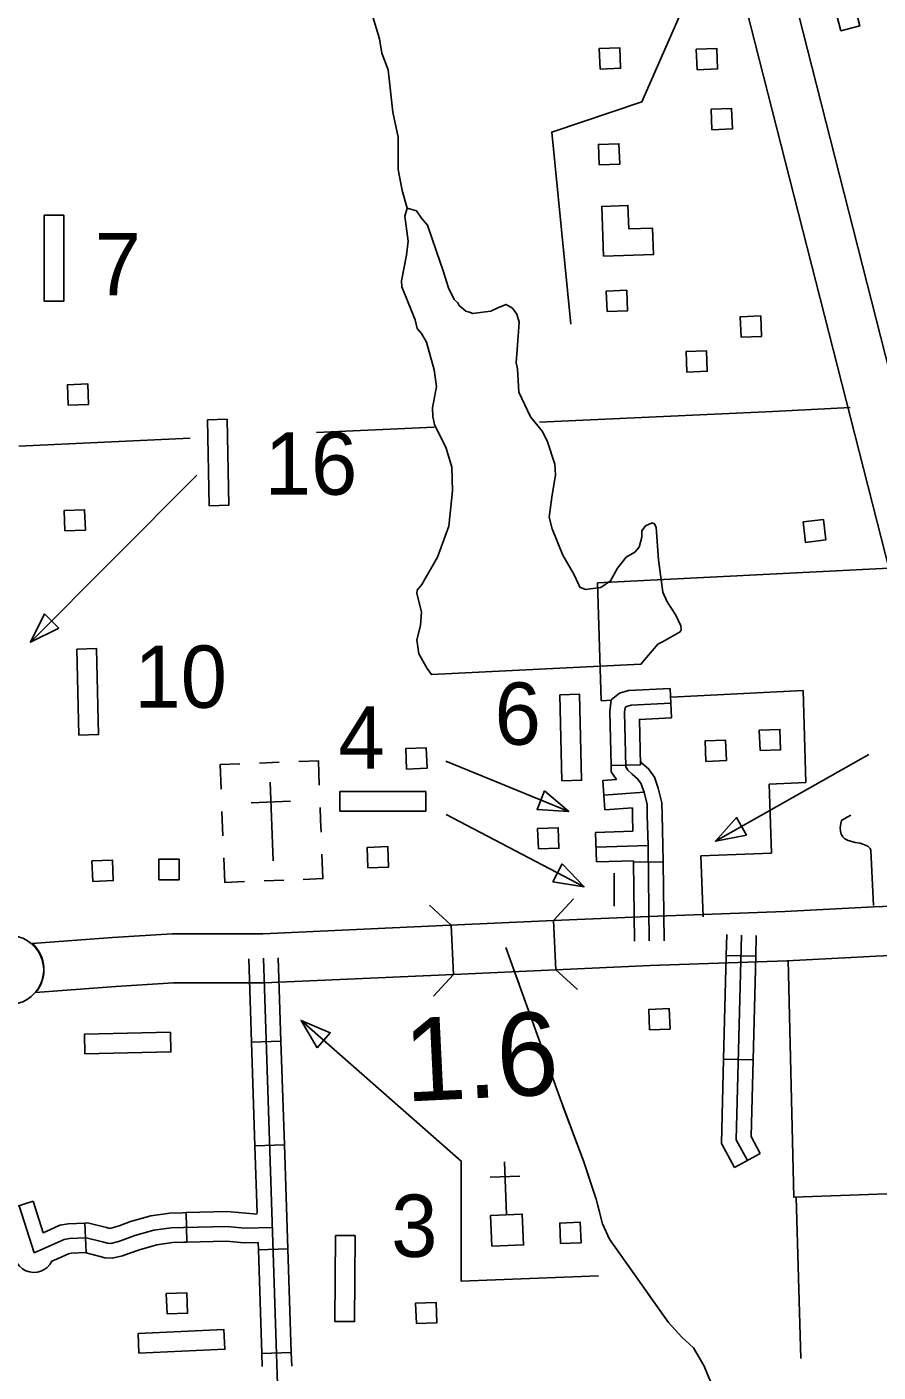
# Model space of a CAD drawing. Extents: x 1671357 to 13005564, y 567358 to 14261451.
# Drawn here: x 12758299.072 to 12758300.518, y 14259939.757 to 14259942.041 of the extents above; entities that cross this region are included whole.
import ezdxf

# ---------------------------------------------------------------- set-up
doc = ezdxf.new("R2010")
doc.units = 0
for name, color, linetype in [('10', 7, 'Continuous'), ('15', 7, 'Continuous'), ('24', 7, 'Continuous'), ('32', 7, 'Continuous'), ('34', 7, 'Continuous'), ('35', 7, 'Continuous'), ('37', 7, 'Continuous'), ('48', 7, 'Continuous'), ('5', 7, 'Continuous'), ('56', 7, 'Continuous'), ('58', 7, 'Continuous'), ('6', 7, 'Continuous')]:
    doc.layers.add(name, color=color, linetype=linetype)

msp = doc.modelspace()

# ---------------------------------------------------------------- linework, layer by layer
at = {"layer": '10'}
for p, q in [((12758299.7965, 14259940.4326), (12758299.7927, 14259940.516)), ((12758299.9707, 14259940.4405), (12758299.9664, 14259940.5238)), ((12758299.9704, 14259940.4404), (12758299.9667, 14259940.5238))]:
    msp.add_line(p, q, dxfattribs=at)
for points in [[(12758300.4677, 14259940.5447), (12758300.5105, 14259940.547), (12758300.6164, 14259940.5512), (12758300.6309, 14259940.5516), (12758300.6426, 14259940.5516), (12758300.6492, 14259940.5516), (12758300.6554, 14259940.5514), (12758300.6635, 14259940.551), (12758300.6733, 14259940.5502), (12758300.7026, 14259940.5476), (12758300.7417, 14259940.5439), (12758300.7807, 14259940.54), (12758300.7871, 14259940.5394), (12758300.7976, 14259940.5383), (12758300.8123, 14259940.537), (12758300.8849, 14259940.4463)], [(12758299.9664, 14259940.5238), (12758300.1277, 14259940.5311), (12758300.3593, 14259940.5391), (12758300.4677, 14259940.5447)], [(12758299.7908, 14259940.5159), (12758299.4729, 14259940.5016), (12758299.3186, 14259940.5016), (12758299.2174, 14259940.4953), (12758299.081, 14259940.485)], [(12758299.9664, 14259940.5238), (12758299.7908, 14259940.5159)], [(12758300.472, 14259940.4614), (12758300.3629, 14259940.4557), (12758300.131, 14259940.4477), (12758299.9707, 14259940.4405)], [(12758300.8849, 14259940.4463), (12758300.8734, 14259940.4474), (12758300.8502, 14259940.4496), (12758300.7895, 14259940.4553), (12758300.7788, 14259940.4563), (12758300.7726, 14259940.457), (12758300.7337, 14259940.4608), (12758300.6949, 14259940.4645), (12758300.666, 14259940.467), (12758300.658, 14259940.4677), (12758300.6523, 14259940.468), (12758300.648, 14259940.4681), (12758300.6426, 14259940.4681), (12758300.632, 14259940.4681), (12758300.6191, 14259940.4678), (12758300.5144, 14259940.4636), (12758300.472, 14259940.4614)], [(12758299.9707, 14259940.4405), (12758299.7969, 14259940.4326)], [(12758299.0868, 14259940.4018), (12758299.2231, 14259940.412), (12758299.3212, 14259940.4182), (12758299.4748, 14259940.4181), (12758299.7969, 14259940.4326)]]:
    msp.add_lwpolyline(points, dxfattribs=at)
msp.add_arc((12758299.0415, 14259940.4404), 0.0595, 319.4609, 48.4838, dxfattribs=at)
at = {"layer": '15'}
msp.add_lwpolyline([(12758300.2887, 14259942.4326), (12758300.6474, 14259941.0247), (12758300.6563, 14259940.9997), (12758300.6752, 14259940.9578), (12758300.5858, 14259940.9531), (12758300.5788, 14259940.9686), (12758300.5675, 14259941.0004), (12758300.2052, 14259942.4222)], dxfattribs=at)
at = {"layer": '24'}
msp.add_circle((12758299.0421, 14259940.44), 0.0584, dxfattribs=at)
at = {"layer": '32'}
for p, q in [((12758300.1645, 14259940.9182), (12758300.167, 14259940.8682)), ((12758300.0643, 14259940.7874), (12758300.1143, 14259940.7886)), ((12758300.0535, 14259940.712), (12758300.0501, 14259940.762)), ((12758300.0396, 14259940.6237), (12758300.038, 14259940.6737)), ((12758300.1025, 14259940.6233), (12758300.1526, 14259940.6239)), ((12758300.3101, 14259940.4635), (12758300.2601, 14259940.4648)), ((12758299.5036, 14259940.3191), (12758299.4535, 14259940.3174)), ((12758300.3055, 14259940.2873), (12758300.2555, 14259940.2886)), ((12758299.5094, 14259940.1429), (12758299.4594, 14259940.1412)), ((12758300.3179, 14259940.1286), (12758300.274, 14259940.1046)), ((12758299.0351, 14259940.0323), (12758299.0829, 14259940.0473)), ((12758299.3436, 14259939.9779), (12758299.3424, 14259940.028)), ((12758299.1729, 14259939.9603), (12758299.1702, 14259940.0103)), ((12758299.5153, 14259939.9667), (12758299.4653, 14259939.9651)), ((12758299.5212, 14259939.7905), (12758299.4711, 14259939.7889))]:
    msp.add_line(p, q, dxfattribs=at)
for points in [[(12758300.1645, 14259940.9182), (12758300.0941, 14259940.9148), (12758300.0788, 14259940.9101), (12758300.0647, 14259940.8986), (12758300.0621, 14259940.8791), (12758300.0643, 14259940.7874)], [(12758300.1658, 14259940.8932), (12758300.0984, 14259940.8899), (12758300.0908, 14259940.8876), (12758300.0882, 14259940.8855), (12758300.0872, 14259940.8777), (12758300.0894, 14259940.7847), (12758300.0929, 14259940.7795), (12758300.1002, 14259940.7727), (12758300.1095, 14259940.7647), (12758300.1155, 14259940.7562), (12758300.1178, 14259940.7493), (12758300.1204, 14259940.7417), (12758300.1256, 14259940.7208), (12758300.1259, 14259940.7027), (12758300.1272, 14259940.6515), (12758300.1293, 14259940.4894)], [(12758300.167, 14259940.8682), (12758300.1125, 14259940.8655), (12758300.1143, 14259940.7886)], [(12758300.0643, 14259940.7874), (12758300.0645, 14259940.7767), (12758300.0735, 14259940.7636)], [(12758300.1142, 14259940.7939), (12758300.1169, 14259940.7914), (12758300.1282, 14259940.7817), (12758300.1382, 14259940.7676), (12758300.1415, 14259940.7572), (12758300.1445, 14259940.7487), (12758300.1505, 14259940.724), (12758300.1509, 14259940.7032), (12758300.1522, 14259940.6519), (12758300.1526, 14259940.6239)], [(12758300.0501, 14259940.762), (12758300.0735, 14259940.7636)], [(12758300.0518, 14259940.737), (12758300.1204, 14259940.7417)], [(12758300.0535, 14259940.712), (12758300.1006, 14259940.7152)], [(12758300.1006, 14259940.7152), (12758300.1009, 14259940.7021), (12758300.1015, 14259940.6757)], [(12758300.038, 14259940.6737), (12758300.1015, 14259940.6757)], [(12758300.0388, 14259940.6487), (12758300.1272, 14259940.6515)], [(12758300.0396, 14259940.6237), (12758300.1025, 14259940.6256)], [(12758300.1025, 14259940.6256), (12758300.1025, 14259940.6233)], [(12758300.1025, 14259940.6233), (12758300.1043, 14259940.489)], [(12758300.1526, 14259940.6239), (12758300.1544, 14259940.4897)], [(12758300.2601, 14259940.4648), (12758300.261, 14259940.5)], [(12758300.2959, 14259940.1166), (12758300.2769, 14259940.1514), (12758300.286, 14259940.4994)], [(12758300.3101, 14259940.4635), (12758300.3111, 14259940.4987)], [(12758299.5036, 14259940.3191), (12758299.4989, 14259940.4607)], [(12758300.2555, 14259940.2886), (12758300.2601, 14259940.4648)], [(12758300.3055, 14259940.2873), (12758300.3101, 14259940.4635)], [(12758299.4535, 14259940.3174), (12758299.4488, 14259940.459)], [(12758299.948, 14259939.0721), (12758299.7733, 14259939.0616), (12758299.769, 14259939.0618), (12758299.7632, 14259939.0639), (12758299.7608, 14259939.0678), (12758299.7573, 14259939.1052), (12758299.757, 14259939.1139), (12758299.7547, 14259939.1218), (12758299.7468, 14259939.1272), (12758299.5455, 14259939.1083), (12758299.5385, 14259939.1071), (12758299.5267, 14259939.1096), (12758299.5198, 14259939.1167), (12758299.5159, 14259939.1313), (12758299.5123, 14259939.235), (12758299.4979, 14259939.7364), (12758299.4738, 14259940.4598)], [(12758299.4594, 14259940.1412), (12758299.4535, 14259940.3174)], [(12758299.5094, 14259940.1429), (12758299.5036, 14259940.3191)], [(12758300.274, 14259940.1046), (12758300.2517, 14259940.1453), (12758300.2555, 14259940.2886)], [(12758300.3179, 14259940.1286), (12758300.3021, 14259940.1575), (12758300.3055, 14259940.2873)], [(12758299.4632, 14259940.0272), (12758299.4594, 14259940.1412)], [(12758299.5153, 14259939.9667), (12758299.5094, 14259940.1429)], [(12758299.059, 14259940.0398), (12758299.0841, 14259939.9598)], [(12758299.0829, 14259940.0473), (12758299.0997, 14259939.9938), (12758299.1048, 14259939.9961), (12758299.1281, 14259940.0067), (12758299.142, 14259940.0088), (12758299.1702, 14259940.0103)], [(12758299.1702, 14259940.0103), (12758299.1749, 14259940.0106), (12758299.207, 14259940.0027), (12758299.2127, 14259940.0011), (12758299.2207, 14259940.0031), (12758299.2289, 14259940.0058), (12758299.2478, 14259940.0128), (12758299.2828, 14259940.0226), (12758299.3149, 14259940.0269), (12758299.337, 14259940.0279), (12758299.3424, 14259940.028)], [(12758299.3424, 14259940.028), (12758299.4124, 14259940.0297), (12758299.4633, 14259940.0252)], [(12758299.0841, 14259939.9598), (12758299.1149, 14259939.9732), (12758299.1353, 14259939.9824), (12758299.1446, 14259939.9838), (12758299.1725, 14259939.9854), (12758299.2006, 14259939.9785), (12758299.2087, 14259939.9762), (12758299.2147, 14259939.9758), (12758299.2276, 14259939.979), (12758299.2372, 14259939.9821), (12758299.2556, 14259939.9889), (12758299.2879, 14259939.998), (12758299.3171, 14259940.002), (12758299.3378, 14259940.0028), (12758299.4116, 14259940.0047), (12758299.4421, 14259940.0019), (12758299.4891, 14259940.0025)], [(12758299.1143, 14259939.9456), (12758299.1251, 14259939.9503), (12758299.1425, 14259939.9582), (12758299.1471, 14259939.9589), (12758299.1729, 14259939.9603)], [(12758299.1702, 14259939.9602), (12758299.1941, 14259939.9543), (12758299.2043, 14259939.9514), (12758299.217, 14259939.9505), (12758299.2345, 14259939.9549), (12758299.2454, 14259939.9584), (12758299.2633, 14259939.9651), (12758299.293, 14259939.9734), (12758299.3194, 14259939.977), (12758299.3387, 14259939.9778), (12758299.3436, 14259939.9779)], [(12758299.3436, 14259939.9779), (12758299.4108, 14259939.9796), (12758299.4411, 14259939.9769), (12758299.4649, 14259939.9772)], [(12758299.4653, 14259939.9651), (12758299.4649, 14259939.9772)], [(12758299.4711, 14259939.7889), (12758299.4653, 14259939.9651)], [(12758299.5212, 14259939.7905), (12758299.5153, 14259939.9667)], [(12758299.4719, 14259939.7666), (12758299.4711, 14259939.7889)], [(12758299.522, 14259939.7674), (12758299.5212, 14259939.7905)]]:
    msp.add_lwpolyline(points, dxfattribs=at)
msp.add_arc((12758299.0841, 14259939.9598), 0.0334, 155.9836, 334.9007, dxfattribs=at)
at = {"layer": '34'}
msp.add_lwpolyline([(12758300.4716, 14259940.7027), (12758300.4614, 14259940.6973), (12758300.4559, 14259940.6941), (12758300.4547, 14259940.6887), (12758300.4537, 14259940.6816), (12758300.4539, 14259940.6759), (12758300.4554, 14259940.6706), (12758300.4579, 14259940.6663), (12758300.4614, 14259940.6628), (12758300.4669, 14259940.66), (12758300.4733, 14259940.6582), (12758300.4793, 14259940.6565), (12758300.4874, 14259940.6551), (12758300.4918, 14259940.6536), (12758300.4976, 14259940.6515), (12758300.5003, 14259940.6502), (12758300.503, 14259940.648), (12758300.5044, 14259940.6464), (12758300.5059, 14259940.6431), (12758300.5103, 14259940.5497)], dxfattribs=at)
at = {"layer": '35'}
for points in [[(12758299.6101, 14259942.6076), (12758299.5419, 14259942.4872), (12758299.5311, 14259942.4644), (12758299.5192, 14259942.4063), (12758299.5187, 14259942.3945), (12758299.5238, 14259942.3465), (12758299.5346, 14259942.2916), (12758299.5441, 14259942.2782), (12758299.5882, 14259942.2525), (12758299.5981, 14259942.2452), (12758299.6064, 14259942.2311), (12758299.6124, 14259942.1774), (12758299.6186, 14259942.1562), (12758299.6303, 14259942.1275), (12758299.6581, 14259942.0639), (12758299.6708, 14259942.0208), (12758299.6747, 14259941.9965), (12758299.6858, 14259941.9685), (12758299.6935, 14259941.8967), (12758299.7025, 14259941.8542), (12758299.7029, 14259941.7993), (12758299.7096, 14259941.7633), (12758299.7181, 14259941.7338)], [(12758299.7181, 14259941.7338), (12758299.7143, 14259941.72), (12758299.7195, 14259941.6773), (12758299.7171, 14259941.6537), (12758299.7081, 14259941.6102), (12758299.7088, 14259941.5998), (12758299.7316, 14259941.5441), (12758299.7352, 14259941.5291), (12758299.7425, 14259941.5207), (12758299.7508, 14259941.5059), (12758299.7639, 14259941.4589), (12758299.7676, 14259941.4309), (12758299.761, 14259941.3944), (12758299.7616, 14259941.38), (12758299.7644, 14259941.3664), (12758299.784, 14259941.326), (12758299.7936, 14259941.2935), (12758299.7951, 14259941.2534), (12758299.789, 14259941.1935), (12758299.7696, 14259941.1411), (12758299.7427, 14259941.0945), (12758299.735, 14259941.0848), (12758299.7345, 14259941.0795), (12758299.7424, 14259941.0479), (12758299.7406, 14259941.0247), (12758299.7345, 14259941.0007), (12758299.7378, 14259940.9771), (12758299.7517, 14259940.9518)], [(12758299.8253, 14259941.5564), (12758299.8179, 14259941.5585), (12758299.8065, 14259941.5681), (12758299.8043, 14259941.5727), (12758299.7981, 14259941.5785), (12758299.7883, 14259941.5982), (12758299.7789, 14259941.627), (12758299.7676, 14259941.6601), (12758299.7526, 14259941.7047), (12758299.7424, 14259941.7164), (12758299.7336, 14259941.7291), (12758299.7181, 14259941.7338)], [(12758300.0012, 14259941.1119), (12758299.9826, 14259941.1444), (12758299.9645, 14259941.1889), (12758299.9591, 14259941.2091), (12758299.9635, 14259941.2428), (12758299.97, 14259941.2809), (12758299.969, 14259941.299), (12758299.9562, 14259941.337), (12758299.9479, 14259941.3545), (12758299.9276, 14259941.3795), (12758299.9076, 14259941.4209), (12758299.9054, 14259941.461), (12758299.903, 14259941.471), (12758299.9064, 14259941.516), (12758299.9081, 14259941.5402), (12758299.9043, 14259941.5535), (12758299.8969, 14259941.5639), (12758299.8859, 14259941.5702), (12758299.8731, 14259941.565), (12758299.86, 14259941.5588), (12758299.8291, 14259941.5549), (12758299.8253, 14259941.5564)], [(12758299.7517, 14259940.9518), (12758299.7591, 14259940.9417), (12758300.1152, 14259940.9592), (12758300.1439, 14259940.9935), (12758300.1518, 14259940.9972), (12758300.1816, 14259941.0141), (12758300.1834, 14259941.0175), (12758300.1828, 14259941.0242), (12758300.1745, 14259941.0423), (12758300.1596, 14259941.0652), (12758300.1523, 14259941.0813), (12758300.1449, 14259941.1363), (12758300.1408, 14259941.1914), (12758300.1382, 14259941.1977), (12758300.1341, 14259941.1995), (12758300.123, 14259941.1941), (12758300.1169, 14259941.1855), (12758300.1167, 14259941.1747), (12758300.1123, 14259941.1582), (12758300.1049, 14259941.1495), (12758300.0899, 14259941.1412), (12758300.0752, 14259941.1225), (12758300.0634, 14259941.101), (12758300.0468, 14259941.0893), (12758300.0209, 14259941.0859), (12758300.0113, 14259941.0902), (12758300.0095, 14259941.0942), (12758300.0012, 14259941.1119)], [(12758299.7591, 14259940.9417), (12758300.1152, 14259940.9592)], [(12758299.8856, 14259940.4782), (12758299.9778, 14259940.2218), (12758300.0183, 14259940.1141), (12758300.0391, 14259940.051), (12758300.0497, 14259940.0088), (12758300.0617, 14259939.9832), (12758300.1619, 14259939.8413), (12758300.1846, 14259939.8167), (12758300.2046, 14259939.7984), (12758300.2221, 14259939.7686), (12758300.2596, 14259939.6789), (12758300.3703, 14259939.568), (12758300.3806, 14259939.5523), (12758300.3962, 14259938.992)], [(12758299.9025, 14259940.4311), (12758299.908, 14259940.416)], [(12758299.9229, 14259940.3745), (12758299.9676, 14259940.2501)], [(12758299.9827, 14259940.2087), (12758300.0183, 14259940.1141), (12758300.028, 14259940.0846)], [(12758300.0412, 14259940.0425), (12758300.0497, 14259940.0088), (12758300.0617, 14259939.9832), (12758300.1016, 14259939.9267)], [(12758300.127, 14259939.8907), (12758300.1619, 14259939.8413), (12758300.1846, 14259939.8167), (12758300.2046, 14259939.7984), (12758300.2103, 14259939.7888)]]:
    msp.add_lwpolyline(points, dxfattribs=at)
at = {"layer": '37'}
for p, q in [((12758299.7946, 14259940.4743), (12758299.7946, 14259940.4743)), ((12758299.9685, 14259940.4821), (12758299.9685, 14259940.4821))]:
    msp.add_line(p, q, dxfattribs=at)
for points in [[(12758300.0004, 14259940.5608), (12758299.9667, 14259940.5238)], [(12758299.7927, 14259940.516), (12758299.7558, 14259940.5498)], [(12758299.9704, 14259940.4404), (12758300.0074, 14259940.4067)], [(12758299.7627, 14259940.3956), (12758299.7965, 14259940.4326)]]:
    msp.add_lwpolyline(points, dxfattribs=at)
at = {"layer": '5'}
for points in [[(12758299.9428, 14259941.3701), (12758300.3389, 14259941.3882), (12758300.4705, 14259941.3949)], [(12758299.5639, 14259941.3528), (12758299.7641, 14259941.3619)], [(12758299.0585, 14259941.3297), (12758299.3491, 14259941.343)], [(12758300.3869, 14259939.7802), (12758300.3787, 14259940.0541)]]:
    msp.add_lwpolyline(points, dxfattribs=at)
at = {"layer": '56'}
for p, q in [((12758299.5006, 14259940.7927), (12758299.4672, 14259940.7914)), ((12758299.485, 14259940.7587), (12758299.4902, 14259940.6253)), ((12758299.4529, 14259940.7241), (12758299.52, 14259940.7267)), ((12758299.571, 14259940.6952), (12758299.5702, 14259940.7158)), ((12758299.4034, 14259940.7093), (12758299.405, 14259940.6676)), ((12758299.4876, 14259940.692), (12758299.4876, 14259940.692)), ((12758299.4876, 14259940.692), (12758299.4876, 14259940.692)), ((12758299.571, 14259940.6952), (12758299.5718, 14259940.6741)), ((12758299.475, 14259940.5913), (12758299.5084, 14259940.5926)), ((12758299.8833, 14259940.1141), (12758299.8867, 14259940.0243)), ((12758299.8592, 14259940.0881), (12758299.9092, 14259940.0901))]:
    msp.add_line(p, q, dxfattribs=at)
for points in [[(12758300.4181, 14259942.1761), (12758300.4504, 14259942.1845), (12758300.4871, 14259942.0431), (12758300.4547, 14259942.0348)], [(12758300.0456, 14259941.9698), (12758300.0443, 14259942.0046), (12758300.0791, 14259942.0059), (12758300.0804, 14259941.9712)], [(12758300.2105, 14259941.9686), (12758300.2092, 14259942.0034), (12758300.244, 14259942.0047), (12758300.2454, 14259941.97)], [(12758300.2357, 14259941.8667), (12758300.2343, 14259941.9014), (12758300.2691, 14259941.9027), (12758300.2705, 14259941.868)], [(12758300.0442, 14259941.807), (12758300.0428, 14259941.8417), (12758300.0777, 14259941.843), (12758300.079, 14259941.8083)], [(12758299.1014, 14259941.7214), (12758299.1347, 14259941.7214), (12758299.1347, 14259941.5754), (12758299.1014, 14259941.5754)], [(12758300.0576, 14259941.5581), (12758300.0562, 14259941.5928), (12758300.0911, 14259941.5941), (12758300.0924, 14259941.5594)], [(12758300.2852, 14259941.5144), (12758300.2838, 14259941.5492), (12758300.3186, 14259941.5505), (12758300.32, 14259941.5158)], [(12758300.1931, 14259941.4552), (12758300.1918, 14259941.4899), (12758300.2266, 14259941.4913), (12758300.2279, 14259941.4566)], [(12758299.1421, 14259941.399), (12758299.1407, 14259941.4337), (12758299.1756, 14259941.4351), (12758299.1769, 14259941.4004)], [(12758299.3786, 14259941.3744), (12758299.412, 14259941.3751), (12758299.4148, 14259941.2291), (12758299.3815, 14259941.2284)], [(12758299.1365, 14259941.1854), (12758299.1351, 14259941.2201), (12758299.1699, 14259941.2215), (12758299.1713, 14259941.1868)], [(12758300.3905, 14259941.2007), (12758300.425, 14259941.2049), (12758300.4292, 14259941.1703), (12758300.3947, 14259941.1661)], [(12758299.126, 14259941.0206), (12758299.1019, 14259941.0446), (12758299.0779, 14259940.9964)], [(12758299.1569, 14259940.9848), (12758299.1903, 14259940.9856), (12758299.1938, 14259940.8396), (12758299.1604, 14259940.8388)], [(12758299.9775, 14259940.9074), (12758300.0109, 14259940.9082), (12758300.0144, 14259940.7622), (12758299.981, 14259940.7614)], [(12758300.3176, 14259940.8125), (12758300.3162, 14259940.8472), (12758300.3511, 14259940.8486), (12758300.3524, 14259940.8138)], [(12758300.2254, 14259940.7942), (12758300.2241, 14259940.8289), (12758300.2589, 14259940.8302), (12758300.2602, 14259940.7955)], [(12758299.7169, 14259940.7811), (12758299.7156, 14259940.8159), (12758299.7504, 14259940.8172), (12758299.7517, 14259940.7825)], [(12758299.6035, 14259940.7094), (12758299.6035, 14259940.7428), (12758299.7495, 14259940.7428), (12758299.7495, 14259940.7094)], [(12758299.9515, 14259940.7442), (12758299.9387, 14259940.7127), (12758299.9924, 14259940.7091)], [(12758300.2945, 14259940.6692), (12758300.2777, 14259940.6988), (12758300.2416, 14259940.6589)], [(12758299.941, 14259940.6455), (12758299.9396, 14259940.6802), (12758299.9745, 14259940.6816), (12758299.9758, 14259940.6468)], [(12758299.6514, 14259940.6133), (12758299.6501, 14259940.648), (12758299.6849, 14259940.6494), (12758299.6863, 14259940.6147)], [(12758299.1839, 14259940.5905), (12758299.1825, 14259940.6252), (12758299.2174, 14259940.6265), (12758299.2187, 14259940.5918)], [(12758299.296, 14259940.5933), (12758299.296, 14259940.628), (12758299.3309, 14259940.628), (12758299.3309, 14259940.5933)], [(12758299.9813, 14259940.6201), (12758299.9655, 14259940.5899), (12758300.0186, 14259940.5813)], [(12758300.1298, 14259940.3383), (12758300.1284, 14259940.373), (12758300.1632, 14259940.3744), (12758300.1646, 14259940.3397)], [(12758299.565, 14259940.3078), (12758299.5874, 14259940.3334), (12758299.5378, 14259940.3543)], [(12758299.1705, 14259940.2976), (12758299.1698, 14259940.331), (12758299.3158, 14259940.3343), (12758299.3166, 14259940.3009)], [(12758299.8617, 14259939.9712), (12758299.8597, 14259940.0233), (12758299.9136, 14259940.0254), (12758299.9157, 14259939.9733)], [(12758299.9785, 14259939.9755), (12758299.9772, 14259940.0102), (12758300.012, 14259940.0116), (12758300.0134, 14259939.9769)], [(12758299.5961, 14259939.9891), (12758299.6295, 14259939.9889), (12758299.6286, 14259939.8429), (12758299.5953, 14259939.8431)], [(12758299.3101, 14259939.8559), (12758299.3088, 14259939.8906), (12758299.3436, 14259939.8919), (12758299.345, 14259939.8572)], [(12758299.7338, 14259939.8395), (12758299.7324, 14259939.8743), (12758299.7672, 14259939.8756), (12758299.7686, 14259939.8409)], [(12758299.2624, 14259939.7892), (12758299.2609, 14259939.8225), (12758299.4068, 14259939.8294), (12758299.4083, 14259939.7961)]]:
    msp.add_lwpolyline(points, close=True, dxfattribs=at)
for points in [[(12758299.9958, 14259941.5365), (12758299.9637, 14259941.8626), (12758300.1169, 14259941.914), (12758300.2171, 14259942.1426)], [(12758299.3608, 14259941.2801), (12758299.0779, 14259940.9964)], [(12758300.502, 14259940.8058), (12758300.2416, 14259940.6589)], [(12758299.4337, 14259940.7901), (12758299.4003, 14259940.7888), (12758299.4019, 14259940.7471)], [(12758299.5337, 14259940.794), (12758299.5671, 14259940.7953), (12758299.5687, 14259940.7536)], [(12758299.7837, 14259940.7943), (12758299.9924, 14259940.7091)], [(12758299.7841, 14259940.7041), (12758300.0186, 14259940.5813)], [(12758299.4415, 14259940.59), (12758299.4081, 14259940.5887), (12758299.4065, 14259940.6304)], [(12758299.5733, 14259940.6369), (12758299.5749, 14259940.5952), (12758299.5415, 14259940.5939)], [(12758300.0697, 14259940.6045), (12758300.0697, 14259940.5483)], [(12758300.0431, 14259939.9209), (12758299.8099, 14259939.9115), (12758299.8099, 14259940.1156), (12758299.5378, 14259940.3543)]]:
    msp.add_lwpolyline(points, dxfattribs=at)
at = {"layer": '58'}
msp.add_lwpolyline([(12758300.0517, 14259941.6518), (12758300.1365, 14259941.6551), (12758300.1347, 14259941.6998), (12758300.0946, 14259941.6983), (12758300.0931, 14259941.7383), (12758300.0484, 14259941.7366)], close=True, dxfattribs=at)
at = {"layer": '6'}
for points in [[(12758300.5369, 14259941.122), (12758300.0416, 14259941.0971)], [(12758300.0416, 14259941.0971), (12758300.0476, 14259940.8973)], [(12758300.0476, 14259940.8973), (12758300.0654, 14259940.8982)], [(12758300.1667, 14259940.9032), (12758300.3908, 14259940.9145)], [(12758300.3908, 14259940.9145), (12758300.3954, 14259940.7584)], [(12758300.3954, 14259940.7584), (12758300.3328, 14259940.7553)], [(12758300.3328, 14259940.7553), (12758300.3369, 14259940.6382)], [(12758300.3369, 14259940.6382), (12758300.217, 14259940.6341)], [(12758300.217, 14259940.6341), (12758300.2207, 14259940.5302)], [(12758300.3651, 14259940.4564), (12758300.3746, 14259940.054), (12758300.6441, 14259940.0638), (12758301.1439, 14259940.0859), (12758301.1853, 14259940.0326), (12758301.2225, 14259939.9861), (12758301.2473, 14259939.9573), (12758301.2719, 14259939.9247), (12758301.3297, 14259939.8543), (12758301.3895, 14259939.795)]]:
    msp.add_lwpolyline(points, dxfattribs=at)

# ---------------------------------------------------------------- texts
at = {"layer": '48'}
msp.add_text('1.6', height=0.14102, rotation=2.7852, dxfattribs=at).set_placement((12758299.7158, 14259940.2165))
at = {"layer": '56'}
for s, height, p in [('7', 0.1058, (12758299.1871, 14259941.5855)), ('16', 0.10577, (12758299.4759, 14259941.247)), ('10', 0.10577, (12758299.2546, 14259940.8852)), ('6', 0.1058, (12758299.8665, 14259940.8225)), ('4', 0.1058, (12758299.601, 14259940.7819)), ('3', 0.1058, (12758299.6908, 14259939.9528))]:
    msp.add_text(s, height=height, dxfattribs=at).set_placement(p)

doc.saveas('drawing.dxf')
